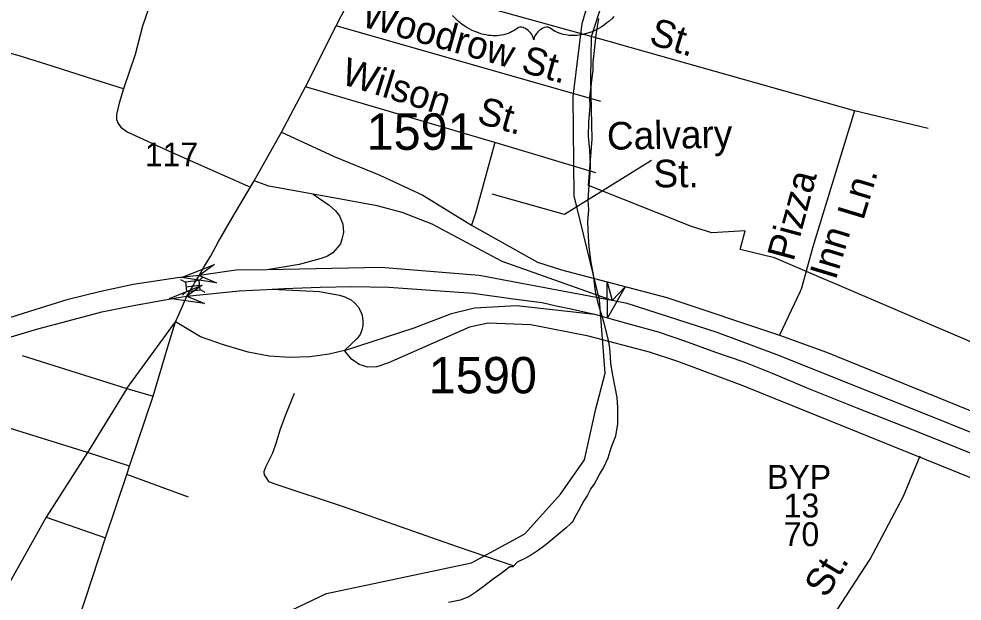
# Model space of a CAD drawing. Extents: x 2260773 to 2342389, y 552869 to 618546.
# Drawn here: x 2301642 to 2304883, y 601248 to 603249 of the extents above; entities that cross this region are included whole.
import ezdxf

# ---------------------------------------------------------------- set-up
doc = ezdxf.new("R2010")
doc.units = 0
for name, color, linetype in [('Exist Boundary Political City Limit New', 7, 'Continuous'), ('Exist Hydrographic Misc Water Feature', 7, 'Continuous'), ('Exist Road Non-System Type 51', 7, 'Continuous'), ('Exist Road Non-System Type 51 Label', 7, 'Continuous'), ('Exist Road Primary Interstate Ramp 1 Lane Attributed', 7, 'Continuous'), ('Exist Road Primary Interstate Structure Ovrhead Sign Attributed CELL', 7, 'Continuous'), ('Exist Road Primary Interstate Structure Standard Bridge CELL', 7, 'Continuous'), ('Exist Road Primary US Divided Attributed', 7, 'Continuous'), ('Exist Road Primary US Label', 7, 'Continuous'), ('Exist Road Primary US Service Attributed', 7, 'Continuous'), ('Exist Road Primary US Shield CELL', 7, 'Continuous'), ('Exist Road Primary US UnDivided 4 Lane Attributed', 7, 'Continuous'), ('Exist Road Secondary Structure Standard Bridge Attributed CELL', 7, 'Continuous'), ('Exist Road Secondary Type 51 Number Label', 7, 'Continuous'), ('Map Preparation Boundary City Limit Buffer Line', 7, 'Continuous')]:
    doc.layers.add(name, color=color, linetype=linetype)

msp = doc.modelspace()

# ---------------------------------------------------------------- linework, layer by layer
at = {"layer": 'Exist Boundary Political City Limit New'}
msp.add_lwpolyline([(2305003.8, 602100.9), (2304238, 602428.4), (2304120.2, 602456.2), (2304138, 602520.3), (2304023, 602514), (2303953.2, 602535.5), (2303598.8, 602677.1), (2303611.5, 602836.4), (2303607, 603042.1), (2303609.5, 603188.8), (2303705.8, 603487.1), (2303784.2, 603717.2), (2303814.8, 603805.8), (2303855.2, 603848.8), (2303902.5, 603873.1), (2304238.2, 603848.2), (2304446, 603840.6), (2304440.8, 603972.1), (2304737.8, 603969.8), (2304798.5, 603860.8), (2304960.5, 603941.8)], dxfattribs=at)
at = {"layer": 'Exist Hydrographic Misc Water Feature'}
for points in [[(2302532.9, 601195.6), (2302699, 601274.5), (2303197.1, 601380), (2303380, 601479.2), (2303503, 601615.5), (2303585, 601733.6), (2303625, 601909.2), (2303657, 602031.8), (2303636.9, 602283.7), (2303550, 602641.2), (2303547.1, 602982.3), (2303577, 603232.9), (2303658, 603508.6), (2303836, 603926), (2303919.1, 604027.8), (2304107.9, 604202.8)], [(2303634, 603250.3), (2303624.8, 603194.1), (2303619.1, 603140.2), (2303613.7, 603100.1), (2303614.2, 603074.1), (2303603.1, 602980), (2303603.3, 602948), (2303599.8, 602894.1), (2303598.6, 602846.1), (2303603.1, 602798.3), (2303603.3, 602774.4), (2303605.3, 602748.1), (2303603.7, 602718.4), (2303600, 602678.3), (2303596.9, 602626.1), (2303599.2, 602594.1), (2303595.7, 602552.1), (2303598.6, 602500.1), (2303600.4, 602466.2), (2303606.8, 602412.5), (2303615.6, 602370.6), (2303622.6, 602312.8), (2303630.6, 602276.7), (2303651.3, 602209.2), (2303668.1, 602139.3), (2303672, 602117.2), (2303674.2, 602087.3), (2303674.9, 602065.3), (2303681.4, 602025.3), (2303689.8, 601983.6), (2303696.2, 601947.7), (2303698.4, 601913.7), (2303698.8, 601885.6), (2303699.1, 601857.6), (2303691.7, 601815.8), (2303676.1, 601773.5), (2303666, 601739.3), (2303650.9, 601707.1), (2303637.1, 601685.3), (2303632.8, 601675), (2303619.5, 601653.1), (2303607.6, 601635), (2303595.7, 601612.8), (2303583.8, 601592.7), (2303574, 601576.4), (2303566.2, 601560.5), (2303556.3, 601542.5), (2303542.6, 601518.2)], [(2302588.3, 601962), (2302559.2, 601891.4), (2302539.9, 601839.1), (2302526.4, 601793.4), (2302513, 601756.8), (2302497, 601724.8), (2302489.2, 601708.9), (2302483.5, 601692.7), (2302485.3, 601682.7), (2302493.8, 601668.9), (2302499.7, 601659.1), (2302527.8, 601649.2), (2302756.2, 601573.8), (2303147.7, 601436.2), (2303342.5, 601369.9)], [(2303542.6, 601518.2), (2303536.9, 601514.2), (2303522.9, 601500.1), (2303481.1, 601465.4), (2303453.6, 601443.2), (2303427.8, 601423.2), (2303400.1, 601404.7), (2303380, 601394.7), (2303354.2, 601382.3), (2303342.5, 601369.9)], [(2303342.5, 601369.9), (2303338.8, 601366), (2303328.5, 601365.9), (2303294.9, 601339.8), (2303273, 601325.6), (2303241.4, 601301.2), (2303211.6, 601278.9), (2303187.7, 601262.7), (2303157.9, 601252.1), (2303117.9, 601244)]]:
    msp.add_lwpolyline(points, dxfattribs=at)
at = {"layer": 'Exist Road Non-System Type 51'}
for p, q in [((2303691, 603165.4), (2302824.9, 603406.3)), ((2303641.8, 602964.8), (2302732.5, 603224.8)), ((2303697.5, 603163.6), (2303691, 603165.4)), ((2304513.7, 602933.2), (2303697.5, 603163.6)), ((2303277.8, 602824.3), (2302627.2, 603015.2)), ((2304766.4, 602872.3), (2304513.7, 602933.2)), ((2303624.2, 602720.7), (2303277.8, 602824.3)), ((2304331.4, 602323.4), (2304325.2, 602310.2)), ((2304325.2, 602310.2), (2304255.3, 602162.8)), ((2302012.7, 601979.6), (2302179.9, 602208.4)), ((2301653.6, 602092.7), (2302012.7, 601979.6)), ((2302012.7, 601979.6), (2301877.5, 601758.9)), ((2302012.7, 601979.6), (2302103, 601952.7)), ((2301877.5, 601758.9), (2301443.1, 601894.2)), ((2301877.5, 601758.9), (2301735.6, 601537.1)), ((2302022.4, 601711.8), (2301877.5, 601758.9)), ((2302225, 601605.7), (2302012.9, 601683.1)), ((2301735.6, 601537.1), (2301549.4, 601204.5)), ((2301735.6, 601537.1), (2301939.5, 601466.2))]:
    msp.add_line(p, q, dxfattribs=at)
for points in [[(2301863.6, 603818), (2301746.3, 603512.7), (2301743.5, 603491.5), (2301747.7, 603478.8), (2301763.3, 603461.8), (2301801.4, 603442), (2301907.4, 603405.3), (2302026, 603357.2), (2302103.4, 603331.4), (2302067, 603224.2), (2302041.6, 603126.6), (2302001.3, 603008.9)], [(2302001.3, 603008.9), (2301899.6, 603040.8), (2301734.3, 603093.8), (2301639, 603123.4), (2301613.5, 603129.8), (2301596.6, 603123.4), (2301581.8, 603104.4), (2301564.8, 603062), (2301524.5, 602934.7), (2301488.5, 602820.2), (2301469.4, 602760.9), (2301452.5, 602731.2), (2301431.3, 602707.9), (2301408, 602690.9), (2301378.3, 602676.1), (2301352.9, 602671.8), (2301319, 602676.1), (2301274.5, 602686.7), (2301218.4, 602703.8)], [(2302001.3, 603008.9), (2301986.5, 602959.6), (2301977.1, 602921), (2301977.1, 602903.1), (2301983.6, 602889.9), (2301992.1, 602877.6), (2302014, 602861.6), (2302168.7, 602789.5), (2302437.8, 602670.8)], [(2304513.7, 602933.2), (2304370, 602465.9), (2304331.5, 602323.5), (2304331.4, 602323.4)], [(2303277.8, 602824.3), (2303211.5, 602581.7), (2303196.7, 602540.3)], [(2304374.2, 601085.1), (2304421.9, 601169), (2304567.7, 601392.4), (2304681.1, 601608.7), (2304739.4, 601747.6)]]:
    msp.add_lwpolyline(points, dxfattribs=at)
at = {"layer": 'Exist Road Non-System Type 51 Label'}
msp.add_lwpolyline([(2303815.4, 602762.4), (2303516.5, 602576.6), (2303268.1, 602646.6)], dxfattribs=at)
at = {"layer": 'Exist Road Primary Interstate Ramp 1 Lane Attributed'}
for points in [[(2302653.7, 602646.9), (2302500.3, 602674.9), (2302450.5, 602692.9)], [(2302653.7, 602646.9), (2302707.9, 602609.5), (2302729.9, 602589.8), (2302743.7, 602572.8), (2302755.3, 602544.2), (2302757.4, 602515.6), (2302752.1, 602492.2), (2302746.8, 602476.3), (2302736.2, 602462.5), (2302720.3, 602445.6), (2302702.3, 602433.9), (2302681.1, 602425.4), (2302604.8, 602405.3), (2302495.7, 602387.2)], [(2303680.3, 602281), (2303302.7, 602415.5), (2303061.9, 602544), (2302959.1, 602583.7), (2302873.3, 602607.1), (2302697.4, 602638.9), (2302653.7, 602646.9)], [(2302512, 602320.4), (2302674.8, 602312), (2302743.7, 602300.3), (2302762, 602294.6), (2302784.6, 602282.7), (2302795.6, 602273.8), (2302807.9, 602260), (2302814.7, 602247.3), (2302821.4, 602231), (2302824.2, 602210.2), (2302824.2, 602195), (2302821, 602179.4), (2302814.3, 602164.6), (2302804.1, 602150.8), (2302761, 602109.2)], [(2302761, 602109.2), (2303000.4, 602187.1), (2303128.7, 602237), (2303208.1, 602256.1), (2303352.3, 602264), (2303619.8, 602234)], [(2302761, 602109.2), (2302708, 602096.5), (2302642.3, 602088), (2302572.3, 602085.9), (2302502.4, 602090.1), (2302429.3, 602103.9), (2302345.6, 602129.4), (2302266.1, 602156.9), (2302179.9, 602208.4)]]:
    msp.add_lwpolyline(points, dxfattribs=at)
at = {"layer": 'Exist Road Primary Interstate Structure Ovrhead Sign Attributed CELL'}
msp.add_lwpolyline([(2303725, 602328.2), (2303665.1, 602222), (2303663.9, 602343.9), (2303680.3, 602281)], close=True, dxfattribs=at)
at = {"layer": 'Exist Road Primary Interstate Structure Standard Bridge CELL'}
for p, q in [((2302197.5, 602353.3), (2302214, 602344.3)), ((2302261.2, 602349.7), (2302275.1, 602362.4)), ((2302203.7, 602300.2), (2302217.7, 602312.9)), ((2302215.8, 602328.6), (2302263, 602334.1)), ((2302264.8, 602318.7), (2302281.3, 602309.6))]:
    msp.add_line(p, q, dxfattribs=at)
msp.add_lwpolyline([(2302217.7, 602312.9), (2302264.8, 602318.4), (2302261.2, 602349.8), (2302214, 602344.3)], close=True, dxfattribs=at)
at = {"layer": 'Exist Road Primary US Divided Attributed'}
for points in [[(2302495.7, 602387.2), (2302388.1, 602385.2), (2302261.6, 602367.5)], [(2303680.3, 602281), (2303223.4, 602367.6), (2302885.2, 602394.4), (2302495.7, 602387.2)], [(2302261.6, 602367.5), (2302187.4, 602359.5), (2302034.8, 602337), (2301923.9, 602312.9), (2301806.7, 602284), (2301678.2, 602243.8), (2301464.5, 602176.3), (2301135.2, 602078.3), (2300788.3, 601970.6), (2300611.6, 601919.1), (2300532, 601897.3)], [(2302219.6, 602295.8), (2302399.4, 602314.5), (2302492.6, 602319.3), (2302512, 602320.4)], [(2302512, 602320.4), (2302553.6, 602322.6), (2302677.3, 602327.4), (2302786.5, 602329), (2302913.4, 602327.4), (2303025.8, 602319.3), (2303202.5, 602306.5), (2303340.7, 602287.2), (2303440.3, 602274.3), (2303488.4, 602263.1), (2303544.7, 602251.8), (2303619.8, 602234)], [(2300520.6, 601826.4), (2300602.3, 601850.9), (2300794.7, 601911.1), (2301109.5, 602004.3), (2301507.9, 602124.9), (2301707.1, 602184.3), (2301811.5, 602211.7), (2301927.1, 602242.2), (2302036.4, 602264.7), (2302189, 602292), (2302219.6, 602295.8)], [(2306457.9, 601206.3), (2305432, 601620.2), (2304253, 602092.7), (2304041, 602171.5), (2303732.6, 602271.1), (2303680.3, 602281)], [(2303619.8, 602234), (2303729.4, 602203.6), (2303838.6, 602173.7), (2303928.6, 602142.5), (2304036.2, 602104), (2304132.6, 602070.2), (2304230.5, 602031.6), (2304355.8, 601978.6), (2304521.3, 601912.7), (2304746.2, 601824.3), (2304935.7, 601747.2), (2305409.6, 601554.3), (2305812.7, 601393.6), (2305909.1, 601355), (2305943.3, 601341.9)]]:
    msp.add_lwpolyline(points, dxfattribs=at)
at = {"layer": 'Exist Road Primary US Service Attributed'}
for points in [[(2302544.1, 602859.4), (2302725.1, 602776.2), (2302882, 602711.6), (2303030.3, 602643.7), (2303196.7, 602540.3), (2303424.5, 602413.1), (2303506.4, 602386.3), (2303868.5, 602292.2), (2304255.3, 602162.8), (2304417.5, 602103.4), (2305880.9, 601509.1), (2306134.2, 601413.7), (2306155.6, 601412.8), (2306174.4, 601415.8), (2306189, 601421.8), (2306271.6, 601475.7)], [(2306887.2, 600412.8), (2306747.5, 600679.3), (2306680.8, 600793.8), (2306629.1, 600867.9), (2306481.5, 600998.5), (2306377.7, 601056.8), (2306131.8, 601179.8), (2304126.9, 601988.9), (2303905.9, 602071.4), (2303809, 602103.4), (2303599.2, 602158.5), (2303401, 602197.7), (2303254.8, 602203.1), (2303190.1, 602190.3), (2302912.5, 602066.8), (2302872.2, 602053), (2302841.5, 602052), (2302810.8, 602061.5), (2302785.3, 602079.5), (2302761, 602109.2)]]:
    msp.add_lwpolyline(points, dxfattribs=at)
at = {"layer": 'Exist Road Primary US Shield CELL'}
msp.add_lwpolyline([(2303686.5, 603256.8), (2303678.9, 603249.2), (2303668.8, 603240.2), (2303662.8, 603235.2), (2303654.1, 603228.7), (2303642.3, 603220.8), (2303630.6, 603214), (2303620.6, 603208.9), (2303611.8, 603205.1), (2303600.4, 603200.8), (2303581.4, 603195.5), (2303574.5, 603194.1), (2303566.3, 603192.9), (2303558.7, 603192.1), (2303551.2, 603191.6), (2303541.2, 603191.6), (2303531.2, 603192.4), (2303521.8, 603193.8), (2303512, 603195.8), (2303501.8, 603198.9), (2303492.5, 603202.5), (2303483, 603207.1), (2303467.1, 603217.2), (2303462.5, 603219.6), (2303460, 603220.3), (2303453.8, 603220.6), (2303448, 603219.4), (2303442.1, 603217), (2303438.5, 603215.1), (2303433.8, 603212), (2303430.1, 603209.1), (2303425.7, 603204.9), (2303422.7, 603201.4), (2303420.4, 603198.7), (2303415.9, 603191.6), (2303414.3, 603188.3), (2303412.6, 603184), (2303411.2, 603177.6), (2303409.1, 603185.6), (2303406.8, 603191), (2303404.1, 603195.5), (2303401.2, 603199.5), (2303396.7, 603204.7), (2303392.7, 603208.6), (2303387.8, 603212.5), (2303382.7, 603215.7), (2303378.5, 603217.8), (2303374.7, 603219.2), (2303370.1, 603220.4), (2303366.3, 603220.7), (2303363.2, 603220.6), (2303358.9, 603219.6), (2303353.1, 603215.4), (2303347.6, 603211.6), (2303341.6, 603207.9), (2303334.5, 603204.1), (2303329.2, 603201.7), (2303323, 603199.2), (2303315.7, 603196.8), (2303307.8, 603194.8), (2303299.7, 603193.2), (2303292.5, 603192), (2303284.9, 603191.3), (2303277.9, 603191.1), (2303270.7, 603191.2), (2303264, 603191.7), (2303256.2, 603192.4), (2303246.4, 603193.8), (2303238.4, 603195.7), (2303229.9, 603198), (2303221.1, 603200.7), (2303211.8, 603204.3), (2303200.1, 603209.4), (2303192, 603213.5), (2303179.1, 603220.9), (2303164.1, 603231.3), (2303152.8, 603240.5), (2303144.4, 603248), (2303132.2, 603260.5)], dxfattribs=at)
at = {"layer": 'Exist Road Primary US UnDivided 4 Lane Attributed'}
for points in [[(2302544.1, 602859.4), (2302627.2, 603015.2), (2302732.5, 603224.8), (2302824.9, 603406.3), (2302896.3, 603543.3), (2302965.4, 603685.8), (2302990, 603729.5), (2303008.7, 603772.8), (2303029.7, 603819.7), (2303047.3, 603868.9), (2303062.5, 603918), (2303071.9, 603957.9), (2303078.9, 603994.2), (2303083.6, 604029.3), (2303088.3, 604071.4), (2303092.9, 604125.3), (2303092.9, 604196.7), (2303094.1, 604249.4)], [(2302450.5, 602692.9), (2302544.1, 602859.4)], [(2302261.6, 602367.5), (2302277.3, 602395.7), (2302300, 602433.1), (2302328.2, 602484.5), (2302381.8, 602576.6), (2302450.5, 602692.9)], [(2302219.6, 602295.8), (2302241.6, 602333.9), (2302245.7, 602341.3), (2302261.6, 602367.5)], [(2302179.9, 602208.4), (2302192.4, 602235.9), (2302219.6, 602295.8)], [(2301176, 599183.7), (2301348.9, 599697.6), (2301474.6, 600047.9), (2301592.3, 600404.5), (2301694.9, 600752.1), (2301824.6, 601116.9), (2301939.5, 601466.2), (2302012.9, 601683.1), (2302022.4, 601711.8), (2302103, 601952.7), (2302152.4, 602118.3), (2302179.9, 602208.4)]]:
    msp.add_lwpolyline(points, dxfattribs=at)
at = {"layer": 'Exist Road Secondary Structure Standard Bridge Attributed CELL'}
for points in [[(2302321.6, 602342.4), (2302201, 602360.7), (2302314.5, 602405.2), (2302261.6, 602367.5)], [(2302279.9, 602271.7), (2302159.1, 602288), (2302271.9, 602334.3), (2302219.6, 602295.8)]]:
    msp.add_lwpolyline(points, close=True, dxfattribs=at)
at = {"layer": 'Map Preparation Boundary City Limit Buffer Line'}
msp.add_lwpolyline([(2305003.8, 602100.9), (2304238, 602428.4), (2304120.2, 602456.2), (2304138, 602520.3), (2304023, 602514), (2303953.2, 602535.5), (2303598.8, 602677.1), (2303611.5, 602836.4), (2303607, 603042.1), (2303609.5, 603188.8), (2303705.8, 603487.1), (2303784.2, 603717.2), (2303814.8, 603805.8), (2303855.2, 603848.8), (2303902.5, 603873.1), (2304238.2, 603848.2), (2304446, 603840.6), (2304440.8, 603972.1), (2304737.8, 603969.8), (2304798.5, 603860.8), (2304960.5, 603941.8)], dxfattribs=at)

# ---------------------------------------------------------------- texts
at = {"layer": 'Exist Road Non-System Type 51 Label'}
for s, rotation, p in [('Woodrow', 344.2613, (2302813.3, 603225.1)), ('St.', 342.8378, (2303803.5, 603164.1)), ('St.', 344.2613, (2303363.7, 603068)), ('Wilson', 342.6471, (2302744.6, 603027.2)), ('St.', 344.0093, (2303211.9, 602892.6)), ('Calvary', 0.9833, (2303663.4, 602799.3)), ('St.', 0.3092, (2303823, 602670)), ('Pizza', 74.8705, (2304303.4, 602413)), ('Ln.', 73.1052, (2304543.3, 602553.8)), ('Inn', 73.1052, (2304448.7, 602348.7)), ('St.', 58.9453, (2304416.7, 601255.7))]:
    msp.add_text(s, height=95, rotation=rotation, dxfattribs=at).set_placement(p)
at = {"layer": 'Exist Road Primary US Label'}
for s, p in [('117', (2302074.9, 602742.2)), ('BYP', (2304213.2, 601634.3)), ('13', (2304270.1, 601535.9)), ('70', (2304270.1, 601437.5))]:
    msp.add_text(s, height=82.02, dxfattribs=at).set_placement(p)
at = {"layer": 'Exist Road Secondary Type 51 Number Label'}
for s, p in [('1591', (2302836.6, 602799.2)), ('1590', (2303050.3, 601962.4))]:
    msp.add_text(s, height=125, dxfattribs=at).set_placement(p)

doc.saveas('drawing.dxf')
